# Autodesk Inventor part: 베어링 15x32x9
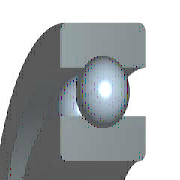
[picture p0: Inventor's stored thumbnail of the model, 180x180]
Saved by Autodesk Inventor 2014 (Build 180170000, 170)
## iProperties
IsCustomPart: 0
Created: 2012-02
Part Number: 베어링 15x32x9
Material: 강철, 연강
Description: 깊은 그루브 볼 베어링
Document SubType Name: Modeling
Standard: KS B 2023
Designer: mduedu
Standards Organization: KS
Language: ko-KR
Size Designation: 6002 - 15 x 32 x 9
Categories: <MemberInstance><Categories><Category DisplayName="샤프트 부품" InternalName="7f7aeb1f-a693-4053-b835-cee3144e0d98" Mnemonic="SHFT"><Category DisplayName="베어링" Inter
Density: 1 g/cm^3
Appearance: Yellow
Author: mduedu
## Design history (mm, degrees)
sketch "스케치" dims "d0" = 4.42 (= -0.26 x WD + 0.26 x BD)
  geometry: L1 (2.29, 11.75)-(6.71, 11.75); L2 (4.5, 11.75)-(4.5, 9.54); L3 (4.5, 11.75)-(4.5, 13.96); L4 (2.858, 10.271)-(0, 10.271); L5 (0, 7.5)-(9, 7.5); L6 (2.858, 13.229)-(0, 13.229); L7 (0, 16)-(9, 16); L8 (9, 7.5)-(9, 10.271); L9 (6.142, 10.271)-(9, 10.271); L10 (6.142, 13.229)-(9, 13.229); L11 (9, 16)-(9, 13.229); L12 (-1.4, 0)-(8.4, 0) reference; L13 (0, -0.3)-(0, 5.3) reference
  constraints: 22 end point, 4 point on line, 2 collinear, 2 perpendicular, 2 symmetric about line, 1 midpoint, 1 parallel, 14 other
  dimensions: "d9" = 15 diameter of L5 L12 (= WD); "d11" = 32 diameter of L7 L12 (= BD); "d12" = 9 distance between parallel lines of L8 L13 (= KB); "d13" = 20.542 diameter of L9 L12 (= 0.326 x BD + 0.674 x WD)
revolve "본체" stored, may be unused: angle "d6" = 90 deg
revolve "볼" stored, may be unused: angle "d7" = 90 deg
pattern_circular "IDS_ARRAYBALL[SIMPL:T]" dims angle "d3" = 360 deg
body "Solid1"
fillet "모깎기1" dims "d1" = 0.3 (= KRS)
other parameters: "WD" = 15 [user parameter; used in 5 equation terms], "BD" = 32 [user parameter; used in 5 equation terms], "KB" = 9 [user parameter; used in 1 equation term], "KRS" = 0.3 [user parameter; used in 1 equation term], "d4" = 0, "d5" = 0, "d8" = 0, "d14" = 0, "d15" = 0, "BBA" = 0 [user parameter], "BC0" = 2850000 [user parameter], "BC" = 5590000 [user parameter], "BR" = 16 (= 0.5 x BD) [user parameter], "WR" = 7.5 (= 0.5 x WD) [user parameter]
